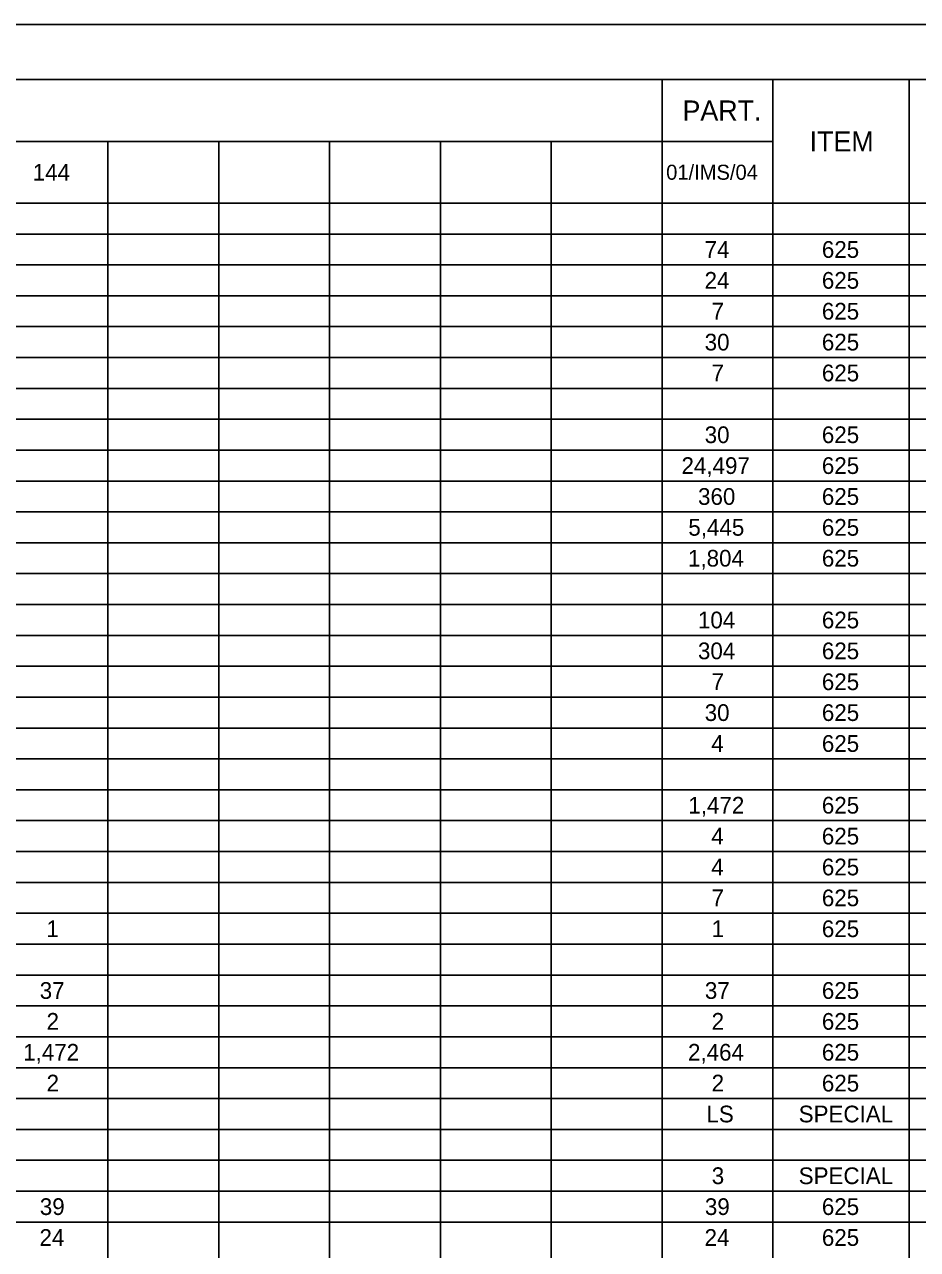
# Model space of a CAD drawing. Extents: x 0 to 34, y 0 to 22.
# Drawn here: x 8.78 to 16.87, y 10.89 to 22 of the extents above; entities that cross this region are included whole.
import ezdxf

# ---------------------------------------------------------------- set-up
doc = ezdxf.new("R2010")
doc.units = 0
for name, color, linetype in [('SH_Border', 7, 'Continuous'), ('SH_Cut_Line', 7, 'Continuous'), ('SH_Text', 7, 'Continuous')]:
    doc.layers.add(name, color=color, linetype=linetype)

msp = doc.modelspace()

# ---------------------------------------------------------------- linework, layer by layer
at = {"layer": 'SH_Border'}
msp.add_lwpolyline([(1.5, 21.5), (33.5, 21.5), (33.5, 0.5), (1.5, 0.5)], close=True, dxfattribs=at)
at = {"layer": 'SH_Cut_Line'}
msp.add_lwpolyline([(0, 0), (34, 0), (34, 22), (0, 22)], close=True, dxfattribs=at)
at = {"layer": 'SH_Text'}
for p, q in [((1.5, 21.5), (32, 21.5)), ((14.56, 21.5), (14.56, 0.5)), ((15.564, 21.5), (15.564, 0.5)), ((16.799, 21.5), (16.799, 0.5)), ((1.5, 20.94), (15.564, 20.94)), ((9.537, 20.94), (9.537, 0.5)), ((10.541, 20.94), (10.541, 0.5)), ((11.546, 20.94), (11.546, 0.5)), ((12.55, 20.94), (12.55, 0.5)), ((13.555, 20.94), (13.555, 0.5)), ((1.5, 20.38), (32, 20.38)), ((1.5, 20.1), (32, 20.1)), ((1.5, 19.82), (32, 19.82)), ((1.5, 19.54), (32, 19.54)), ((1.5, 19.26), (32, 19.26)), ((1.5, 18.98), (32, 18.98)), ((1.5, 18.7), (32, 18.7)), ((1.5, 18.42), (32, 18.42)), ((1.5, 18.14), (32, 18.14)), ((1.5, 17.86), (32, 17.86)), ((1.5, 17.58), (32, 17.58)), ((1.5, 17.3), (32, 17.3)), ((1.5, 17.02), (32, 17.02)), ((1.5, 16.74), (32, 16.74)), ((1.5, 16.46), (32, 16.46)), ((1.5, 16.18), (32, 16.18)), ((1.5, 15.9), (32, 15.9)), ((1.5, 15.62), (32, 15.62)), ((1.5, 15.34), (32, 15.34)), ((1.5, 15.06), (32, 15.06)), ((1.5, 14.78), (32, 14.78)), ((1.5, 14.5), (32, 14.5)), ((1.5, 14.22), (32, 14.22)), ((1.5, 13.94), (32, 13.94)), ((1.5, 13.66), (32, 13.66)), ((1.5, 13.38), (32, 13.38)), ((1.5, 13.1), (32, 13.1)), ((1.5, 12.82), (32, 12.82)), ((1.5, 12.54), (32, 12.54)), ((1.5, 12.26), (32, 12.26)), ((1.5, 11.98), (32, 11.98)), ((1.5, 11.7), (32, 11.7)), ((1.5, 11.42), (32, 11.42)), ((1.5, 11.14), (32, 11.14))]:
    msp.add_line(p, q, dxfattribs=at)

# ---------------------------------------------------------------- texts
for s, height, p in [('PART.', 0.1818, (14.744, 21.129)), ('ITEM', 0.1818, (15.896, 20.849)), ('144', 0.1515, (8.856, 20.584)), ('01/IMS/04', 0.1364, (14.596, 20.592)), ('74', 0.1515, (14.944, 19.884)), ('625', 0.1515, (16.007, 19.884)), ('24', 0.1515, (14.944, 19.604)), ('625', 0.1515, (16.007, 19.604)), ('7', 0.152, (15.007, 19.324)), ('625', 0.1515, (16.007, 19.324)), ('30', 0.1515, (14.945, 19.044)), ('625', 0.1515, (16.007, 19.044)), ('7', 0.152, (15.007, 18.764)), ('625', 0.1515, (16.007, 18.764)), ('30', 0.1515, (14.945, 18.204)), ('625', 0.1515, (16.007, 18.204)), ('24,497', 0.1515, (14.735, 17.924)), ('625', 0.1515, (16.007, 17.924)), ('360', 0.1515, (14.885, 17.644)), ('625', 0.1515, (16.007, 17.644)), ('5,445', 0.1515, (14.797, 17.364)), ('625', 0.1515, (16.007, 17.364)), ('1,804', 0.1515, (14.794, 17.084)), ('625', 0.1515, (16.007, 17.084)), ('104', 0.1515, (14.884, 16.524)), ('625', 0.1515, (16.007, 16.524)), ('304', 0.1515, (14.884, 16.244)), ('625', 0.1515, (16.007, 16.244)), ('7', 0.152, (15.007, 15.964)), ('625', 0.1515, (16.007, 15.964)), ('30', 0.1515, (14.945, 15.684)), ('625', 0.1515, (16.007, 15.684)), ('4', 0.152, (15.005, 15.404)), ('625', 0.1515, (16.007, 15.404)), ('1,472', 0.1515, (14.797, 14.844)), ('625', 0.1515, (16.007, 14.844)), ('4', 0.152, (15.005, 14.564)), ('625', 0.1515, (16.007, 14.564)), ('4', 0.152, (15.005, 14.284)), ('625', 0.1515, (16.007, 14.284)), ('7', 0.152, (15.007, 14.004)), ('625', 0.1515, (16.007, 14.004)), ('1', 0.152, (8.98, 13.724)), ('1', 0.152, (15.008, 13.724)), ('625', 0.1515, (16.007, 13.724)), ('37', 0.1515, (8.919, 13.164)), ('37', 0.1515, (14.947, 13.164)), ('625', 0.1515, (16.007, 13.164)), ('2', 0.152, (8.981, 12.884)), ('2', 0.152, (15.008, 12.884)), ('625', 0.1515, (16.007, 12.884)), ('1,472', 0.1515, (8.769, 12.604)), ('2,464', 0.1515, (14.794, 12.604)), ('625', 0.1515, (16.007, 12.604)), ('2', 0.152, (8.981, 12.324)), ('2', 0.152, (15.008, 12.324)), ('625', 0.1515, (16.007, 12.324)), ('LS', 0.1515, (14.961, 12.044)), ('SPECIAL', 0.1515, (15.797, 12.044)), ('3', 0.152, (15.009, 11.484)), ('SPECIAL', 0.1515, (15.797, 11.484)), ('39', 0.1515, (8.92, 11.204)), ('39', 0.1515, (14.947, 11.204)), ('625', 0.1515, (16.007, 11.204)), ('24', 0.1515, (8.917, 10.924)), ('24', 0.1515, (14.944, 10.924)), ('625', 0.1515, (16.007, 10.924))]:
    msp.add_text(s, height=height, dxfattribs=at).set_placement(p)

doc.saveas('drawing.dxf')
